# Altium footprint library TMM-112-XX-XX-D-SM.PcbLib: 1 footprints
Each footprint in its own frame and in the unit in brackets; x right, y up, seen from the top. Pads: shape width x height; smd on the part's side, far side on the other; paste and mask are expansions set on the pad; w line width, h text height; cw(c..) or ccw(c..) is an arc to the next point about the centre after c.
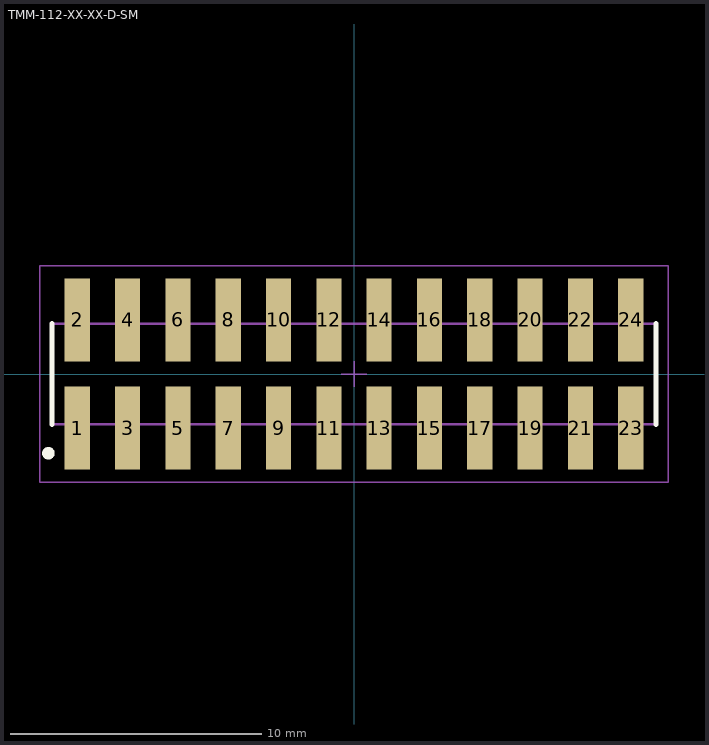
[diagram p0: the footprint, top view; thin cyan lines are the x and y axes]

## TMM-112-XX-XX-D-SM [mm] "2.00mm pitch, 24 pin, terminal strip; double row, SMT"
height 2.77
pads (24):
  rect 1x3.3 smd mask+0: 1(-11,-2.15) 2(-11,2.15) 3(-9,-2.15) 4(-9,2.15) 5(-7,-2.15) 6(-7,2.15) 7(-5,-2.15) 8(-5,2.15) 9(-3,-2.15) 10(-3,2.15) 11(-1,-2.15) 12(-1,2.15) 13(1,-2.15) 14(1,2.15) 15(3,-2.15) 16(3,2.15) 17(5,-2.15) 18(5,2.15) 19(7,-2.15) 20(7,2.15) 21(9,-2.15) 22(9,2.15) 23(11,-2.15) 24(11,2.15)
Top Overlay:
  circle w0.25: c-12.15,-3.15 r0.125
  lines w0.2: -12,-2 -12,2 ; 12,-2 12,2
Mechanical 12:
  lines w0.001: -12,-2 12,-2 12,2 -12,2 -12,-2
Mechanical 13:
  lines w0.1: -12,-2 12,-2 12,2 -12,2 -12,-2
  text ".Designator" at 0,-0.127 h1.52
Mechanical 15:
  lines w0.05: -0.5,0 0.5,0 ; 0,-0.5 0,0.5 ; -12.5,-4.3 12.5,-4.3 12.5,4.3 -12.5,4.3 -12.5,-4.3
